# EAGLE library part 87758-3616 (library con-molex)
36 Pin - 2mm Dual Row Single Wafer, Vertical T/H HDR Source: http://www.molex.com/pdm_docs/sd/877580616_sd.pdf
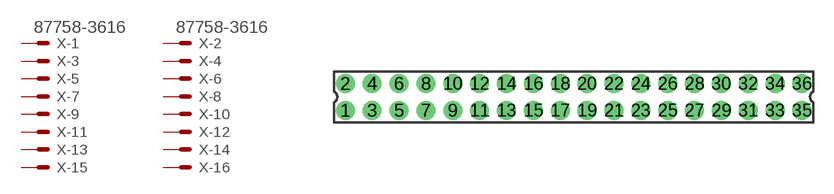
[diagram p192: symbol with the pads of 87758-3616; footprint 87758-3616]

Designator prefix X; gates -1=MV -2=MV -3=M -4=M -5=M -6=M -7=M -8=M -9=M -10=M -11=M -12=M -13=M -14=M -15=M -16=M -17=M -18=M -19=M -20=M -21=M -22=M -23=M -24=M -25=M -26=M -27=M -28=M -29=M -30=M -31=M -32=M -33=M -34=M -35=M -36=M

## 87758-3616 (MPN: 87758-3616; OC_FARNELL: unknown; OC_NEWARK: 25M5688)  [87758-3616]
1  -1:S  pas
2  -2:S  pas
3  -3:S  pas
4  -4:S  pas
5  -5:S  pas
6  -6:S  pas
7  -7:S  pas
8  -8:S  pas
9  -9:S  pas
10  -10:S  pas
11  -11:S  pas
12  -12:S  pas
13  -13:S  pas
14  -14:S  pas
15  -15:S  pas
16  -16:S  pas
17  -17:S  pas
18  -18:S  pas
19  -19:S  pas
20  -20:S  pas
21  -21:S  pas
22  -22:S  pas
23  -23:S  pas
24  -24:S  pas
25  -25:S  pas
26  -26:S  pas
27  -27:S  pas
28  -28:S  pas
29  -29:S  pas
30  -30:S  pas
31  -31:S  pas
32  -32:S  pas
33  -33:S  pas
34  -34:S  pas
35  -35:S  pas
36  -36:S  pas

## Footprint 87758-3616 (pad centres in mm)
36 Pin - 2mm Dual Row Single Wafer, Vertical T/H HDR Source: http://www.molex.com/pdm_docs/sd/877580616_sd.pdf
drill 0.9 pad 1.27 round: 1 -17,-1; 2 -17,1; 3 -15,-1; 4 -15,1; 5 -13,-1; 6 -13,1; 7 -11,-1; 8 -11,1; 9 -9,-1; 10 -9,1; 11 -7,-1; 12 -7,1; 13 -5,-1; 14 -5,1; 15 -3,-1; 16 -3,1; 17 -1,-1; 18 -1,1; 19 1,-1; 20 1,1; 21 3,-1; 22 3,1; 23 5,-1; 24 5,1; 25 7,-1; 26 7,1; 27 9,-1; 28 9,1; 29 11,-1; 30 11,1; 31 13,-1; 32 13,1; 33 15,-1; 34 15,1; 35 17,-1; 36 17,1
